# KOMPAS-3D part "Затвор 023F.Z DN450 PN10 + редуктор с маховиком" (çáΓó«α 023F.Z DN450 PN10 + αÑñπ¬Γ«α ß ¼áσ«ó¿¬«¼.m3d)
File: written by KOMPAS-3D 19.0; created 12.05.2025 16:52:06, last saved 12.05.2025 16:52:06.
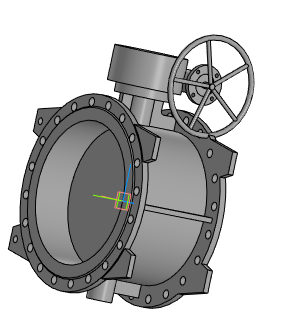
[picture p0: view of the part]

Document properties: Полное имя файла: Затвор 023F.Z DN450 PN10 + редуктор с маховиком.a3d

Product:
- Part/product: Затвор 023F.Z DN450 PN10 + редуктор с маховиком
    Масса: 224.891

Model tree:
1. Операция без истории:1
